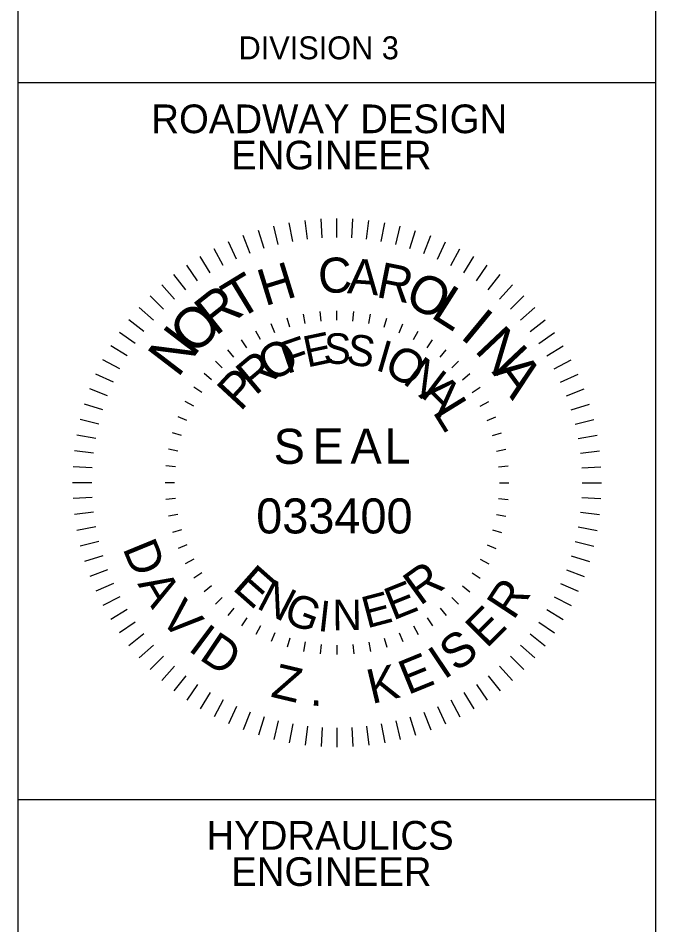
# Model space of a CAD drawing. Extents: x 24 to 2046, y 15 to 1115.
# Drawn here: x 1586.4 to 1686.5, y 834.5 to 976.8 of the extents above; entities that cross this region are included whole.
import ezdxf

# ---------------------------------------------------------------- set-up
doc = ezdxf.new("R2010")
doc.units = 0
doc.layers.add('Sheet_RDY_PE_Seal_Cell', color=7, linetype='Continuous')
doc.layers.add('z - Construction', color=7, linetype='Continuous')

msp = doc.modelspace()

# ---------------------------------------------------------------- linework, layer by layer
at = {"layer": 'Sheet_RDY_PE_Seal_Cell'}
for p, q in [((1631.81, 942.06), (1631.45, 945.03)), ((1634.13, 942.27), (1633.95, 945.26)), ((1636.45, 942.34), (1636.45, 945.34)), ((1638.77, 942.27), (1638.96, 945.26)), ((1641.09, 942.06), (1641.45, 945.03)), ((1625, 940.6), (1624.11, 943.46)), ((1627.24, 941.22), (1626.52, 944.13)), ((1629.52, 941.71), (1628.97, 944.66)), ((1643.39, 941.71), (1643.93, 944.66)), ((1645.66, 941.22), (1646.38, 944.13)), ((1647.9, 940.59), (1648.79, 943.46)), ((1622.81, 939.84), (1621.74, 942.64)), ((1650.09, 939.84), (1651.16, 942.64)), ((1618.57, 937.93), (1617.18, 940.58)), ((1620.66, 938.95), (1619.43, 941.68)), ((1652.24, 938.95), (1653.47, 941.68)), ((1654.33, 937.93), (1655.73, 940.58)), ((1616.55, 936.79), (1614.99, 939.36)), ((1656.35, 936.79), (1657.91, 939.36)), ((1614.59, 935.53), (1612.89, 937.99)), ((1658.31, 935.53), (1660.01, 937.99)), ((1612.72, 934.15), (1610.87, 936.51)), ((1660.18, 934.15), (1662.03, 936.51)), ((1610.94, 932.66), (1608.95, 934.91)), ((1661.97, 932.66), (1663.96, 934.91)), ((1609.24, 931.07), (1607.12, 933.19)), ((1663.66, 931.07), (1665.78, 933.19)), ((1607.65, 929.37), (1605.41, 931.36)), ((1633.95, 929.22), (1633.81, 930.71)), ((1636.45, 929.35), (1636.45, 930.84)), ((1638.95, 929.22), (1639.09, 930.71)), ((1665.25, 929.37), (1667.49, 931.36)), ((1606.16, 927.59), (1603.8, 929.44)), ((1629.05, 928.25), (1628.62, 929.68)), ((1631.48, 928.86), (1631.19, 930.33)), ((1641.42, 928.86), (1641.72, 930.33)), ((1643.85, 928.25), (1644.29, 929.68)), ((1666.74, 927.59), (1669.1, 929.44)), ((1626.7, 927.4), (1626.12, 928.79)), ((1646.2, 927.4), (1646.78, 928.79)), ((1604.78, 925.72), (1602.32, 927.42)), ((1622.29, 925.05), (1621.46, 926.3)), ((1624.44, 926.34), (1623.73, 927.66)), ((1648.46, 926.34), (1649.17, 927.66)), ((1650.61, 925.05), (1651.44, 926.3)), ((1668.12, 925.72), (1670.58, 927.42)), ((1603.52, 923.77), (1600.96, 925.32)), ((1669.38, 923.77), (1671.95, 925.32)), ((1620.28, 923.56), (1619.33, 924.72)), ((1652.62, 923.56), (1653.57, 924.72)), ((1602.38, 921.74), (1599.73, 923.13)), ((1618.43, 921.88), (1617.37, 922.94)), ((1654.47, 921.88), (1655.53, 922.94)), ((1670.52, 921.74), (1673.18, 923.14)), ((1601.36, 919.65), (1598.63, 920.88)), ((1616.75, 920.03), (1615.59, 920.98)), ((1656.15, 920.03), (1657.31, 920.98)), ((1671.54, 919.65), (1674.27, 920.88)), ((1600.47, 917.5), (1597.67, 918.57)), ((1615.26, 918.02), (1614.01, 918.85)), ((1657.64, 918.02), (1658.89, 918.85)), ((1672.43, 917.5), (1675.23, 918.57)), ((1613.97, 915.87), (1612.65, 916.58)), ((1658.93, 915.87), (1660.25, 916.58)), ((1599.71, 915.31), (1596.85, 916.2)), ((1673.19, 915.31), (1676.05, 916.2)), ((1599.09, 913.07), (1596.18, 913.79)), ((1612.9, 913.61), (1611.52, 914.18)), ((1660, 913.61), (1661.38, 914.18)), ((1673.81, 913.07), (1676.72, 913.79)), ((1598.6, 910.8), (1595.65, 911.34)), ((1612.06, 911.26), (1610.63, 911.69)), ((1660.84, 911.26), (1662.27, 911.69)), ((1674.3, 910.8), (1677.25, 911.34)), ((1598.25, 908.5), (1595.28, 908.86)), ((1611.46, 908.83), (1609.99, 909.12)), ((1661.45, 908.83), (1662.92, 909.12)), ((1674.65, 908.5), (1677.62, 908.86)), ((1598.04, 906.18), (1595.05, 906.36)), ((1611.09, 906.36), (1609.6, 906.5)), ((1661.81, 906.36), (1663.3, 906.5)), ((1674.86, 906.18), (1677.85, 906.36)), ((1597.97, 903.86), (1594.97, 903.86)), ((1610.97, 903.86), (1609.47, 903.86)), ((1661.93, 903.86), (1663.43, 903.86)), ((1674.93, 903.86), (1677.93, 903.86)), ((1598.04, 901.54), (1595.05, 901.36)), ((1611.09, 901.36), (1609.6, 901.22)), ((1661.81, 901.36), (1663.3, 901.22)), ((1674.86, 901.54), (1677.85, 901.36)), ((1598.25, 899.22), (1595.28, 898.86)), ((1674.65, 899.22), (1677.62, 898.86)), ((1611.46, 898.89), (1609.99, 898.6)), ((1661.45, 898.89), (1662.92, 898.6)), ((1598.6, 896.92), (1595.65, 896.38)), ((1612.06, 896.46), (1610.63, 896.03)), ((1660.84, 896.46), (1662.27, 896.03)), ((1674.3, 896.92), (1677.25, 896.38)), ((1599.09, 894.65), (1596.18, 893.93)), ((1612.91, 894.11), (1611.52, 893.53)), ((1660, 894.11), (1661.38, 893.53)), ((1673.81, 894.65), (1676.72, 893.93)), ((1599.71, 892.41), (1596.85, 891.52)), ((1673.19, 892.41), (1676.05, 891.52)), ((1613.97, 891.85), (1612.65, 891.14)), ((1658.93, 891.85), (1660.25, 891.14)), ((1600.47, 890.21), (1597.67, 889.15)), ((1615.26, 889.7), (1614.01, 888.87)), ((1657.64, 889.7), (1658.89, 888.87)), ((1672.43, 890.21), (1675.23, 889.15)), ((1601.36, 888.07), (1598.63, 886.84)), ((1671.54, 888.07), (1674.27, 886.84)), ((1616.75, 887.69), (1615.59, 886.74)), ((1656.15, 887.69), (1657.31, 886.74)), ((1602.38, 885.98), (1599.73, 884.59)), ((1618.43, 885.84), (1617.37, 884.78)), ((1654.47, 885.84), (1655.53, 884.78)), ((1670.52, 885.98), (1673.18, 884.59)), ((1603.52, 883.95), (1600.96, 882.4)), ((1620.28, 884.16), (1619.33, 883)), ((1652.62, 884.16), (1653.57, 883)), ((1669.38, 883.95), (1671.95, 882.4)), ((1622.29, 882.67), (1621.46, 881.42)), ((1650.61, 882.67), (1651.44, 881.42)), ((1604.78, 882), (1602.32, 880.3)), ((1624.44, 881.39), (1623.73, 880.06)), ((1648.46, 881.38), (1649.17, 880.06)), ((1668.12, 882), (1670.58, 880.3)), ((1606.16, 880.13), (1603.8, 878.28)), ((1626.7, 880.31), (1626.12, 878.93)), ((1629.05, 879.47), (1628.62, 878.04)), ((1643.85, 879.47), (1644.29, 878.04)), ((1646.2, 880.31), (1646.78, 878.93)), ((1666.74, 880.13), (1669.1, 878.28)), ((1607.65, 878.35), (1605.41, 876.36)), ((1631.48, 878.87), (1631.19, 877.39)), ((1633.95, 878.5), (1633.81, 877.01)), ((1636.45, 878.38), (1636.45, 876.88)), ((1638.95, 878.5), (1639.09, 877.01)), ((1641.42, 878.86), (1641.72, 877.39)), ((1665.25, 878.35), (1667.49, 876.36)), ((1609.24, 876.65), (1607.12, 874.53)), ((1663.66, 876.65), (1665.78, 874.53)), ((1610.94, 875.06), (1608.95, 872.82)), ((1661.97, 875.06), (1663.96, 872.82)), ((1612.72, 873.57), (1610.87, 871.21)), ((1614.59, 872.19), (1612.89, 869.73)), ((1658.31, 872.19), (1660.01, 869.73)), ((1660.18, 873.57), (1662.03, 871.21)), ((1616.55, 870.93), (1614.99, 868.37)), ((1656.35, 870.93), (1657.91, 868.37)), ((1618.57, 869.79), (1617.18, 867.13)), ((1654.33, 869.79), (1655.73, 867.13)), ((1620.66, 868.77), (1619.43, 866.04)), ((1652.24, 868.77), (1653.47, 866.04)), ((1622.81, 867.88), (1621.74, 865.08)), ((1625.01, 867.12), (1624.11, 864.26)), ((1627.24, 866.5), (1626.52, 863.59)), ((1645.66, 866.5), (1646.38, 863.59)), ((1647.9, 867.12), (1648.79, 864.26)), ((1650.09, 867.88), (1651.16, 865.08)), ((1629.52, 866.01), (1628.97, 863.06)), ((1631.81, 865.66), (1631.45, 862.69)), ((1634.13, 865.45), (1633.95, 862.46)), ((1636.45, 865.38), (1636.45, 862.38)), ((1638.77, 865.45), (1638.95, 862.46)), ((1641.09, 865.66), (1641.45, 862.69)), ((1643.39, 866.01), (1643.93, 863.06))]:
    msp.add_line(p, q, dxfattribs=at)
at = {"layer": 'z - Construction'}
for p, q in [((1586.43, 52.48), (1586.45, 1077.48)), ((1686.43, 52.48), (1686.45, 1077.48)), ((1686.48, 966.61), (1586.48, 966.61)), ((1686.42, 854.11), (1586.43, 854.11))]:
    msp.add_line(p, q, dxfattribs=at)

# ---------------------------------------------------------------- texts
at = {"layer": 'Sheet_RDY_PE_Seal_Cell'}
for s, height, rotation, p in [('C', 5.5, 2.964, (1633.62, 933.54)), ('H', 5.73, 17.1424, (1625.12, 931.53)), ('A', 5.51, 355.8747, (1637.98, 933.61)), ('R', 5.6, 348.7855, (1642.44, 933.03)), ('T', 6.13, 31.3209, (1620.94, 929.28)), ('O', 5.96, 334.607, (1646.8, 931.91)), ('R', 6.3, 38.4101, (1617.39, 926.75)), ('L', 6.16, 327.5178, (1650.96, 929.93)), ('O', 6.4, 45.4993, (1614.14, 923.65)), ('I', 6.32, 320.4286, (1655.58, 926.69)), ('N', 6.4, 52.5886, (1611.46, 920.2)), ('N', 6.41, 313.3394, (1657.85, 924.57)), ('F', 5.04, 18.9979, (1628.61, 920.88)), ('E', 4.9, 11.9657, (1631.77, 921.92)), ('S', 4.8, 357.9015, (1634.28, 922.59)), ('S', 4.86, 350.8694, (1637.7, 922.54)), ('O', 5.39, 33.0621, (1626.25, 919.47)), ('I', 4.98, 343.8373, (1642.31, 921.57)), ('O', 5.32, 329.773, (1643.52, 921.32)), ('R', 5.53, 40.0942, (1623.61, 917.42)), ('N', 5.48, 322.7409, (1646.55, 919.6)), ('A', 6.39, 306.2501, (1660.65, 921.23)), ('P', 5.6, 47.1264, (1621.29, 914.92)), ('A', 5.58, 315.7088, (1649.15, 917.51)), ('L', 5.51, 301.6445, (1651.36, 915)), ('S', 5.5, 0, (1626.51, 906.82)), ('E', 5.5, 0, (1632.6, 906.87)), ('A', 5.5, 0, (1638.56, 906.85)), ('L', 5.5, 0, (1643.88, 906.87)), ('033400', 5.497, 0, (1623.78, 895.9)), ('D', 5.4, 292.3254, (1602.76, 893.57)), ('E', 5.55, 318.5439, (1619.87, 887.2)), ('R', 5.45, 35.8972, (1649.47, 884.45)), ('A', 5.4, 300.5566, (1605.09, 887.99)), ('N', 5.25, 332.6082, (1623.63, 884.28)), ('E', 5.11, 21.833, (1645.24, 882.21)), ('R', 5.4, 56.6621, (1664.15, 882.15)), ('E', 4.95, 14.8009, (1641.14, 880.98)), ('V', 5.4, 311.7772, (1608.53, 882.47)), ('G', 5.07, 339.6403, (1627.82, 882.06)), ('I', 4.83, 353.7045, (1633.33, 880.62)), ('N', 4.8, 0.7366, (1635.75, 880.68)), ('E', 5.4, 45.3772, (1659.96, 877.74)), ('I', 5.4, 323.2372, (1612.93, 877.65)), ('D', 5.4, 326.1338, (1614.66, 876.24)), ('S', 5.4, 36.7617, (1655.14, 874.04)), ('I', 5.4, 33.8651, (1653.23, 872.88)), ('E', 5.4, 22.1784, (1647.58, 870.52)), ('Z', 5.4, 346.6654, (1625.91, 870.31)), ('K', 5.4, 13.3335, (1641.9, 869.11)), ('.', 5.4, 358.5162, (1632.15, 868.88))]:
    msp.add_text(s, height=height, rotation=rotation, dxfattribs=at).set_placement(p)
at = {"layer": 'z - Construction'}
for s, height, p in [('DIVISION 3', 3.6, (1621.01, 970.3)), ('ROADWAY DESIGN', 4.5, (1607.32, 958.71)), ('ENGINEER', 4.5, (1619.85, 953.02)), ('HYDRAULICS', 4.5, (1615.97, 846.28)), ('ENGINEER', 4.5, (1619.85, 840.59))]:
    msp.add_text(s, height=height, rotation=0, dxfattribs=at).set_placement(p)

doc.saveas('drawing.dxf')
